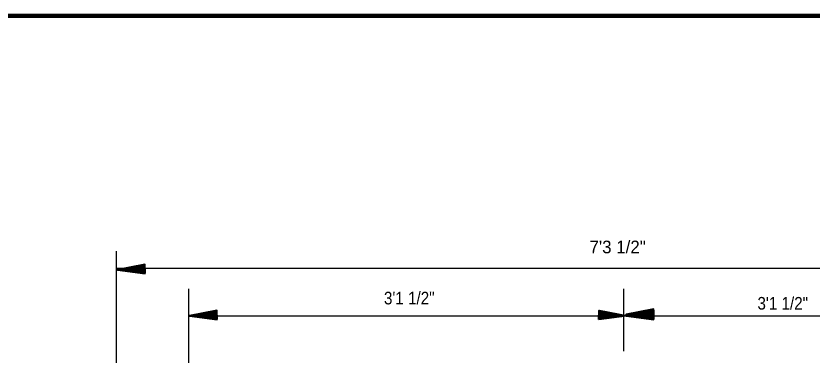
# Model space of a CAD drawing. Extents: x 895.6 to 930.4, y -2278.6 to -2254.7.
# Drawn here: x 911.41 to 919.51, y -2259.61 to -2256.16 of the extents above; entities that cross this region are included whole.
import ezdxf

# ---------------------------------------------------------------- set-up
doc = ezdxf.new("R2010")
doc.units = 0
doc.header["$LTSCALE"] = 0.051
doc.layers.add('1', color=7, linetype='Continuous', lineweight=70)
doc.layers.add('3', color=7, linetype='Continuous', lineweight=40)

msp = doc.modelspace()

# ---------------------------------------------------------------- hatches: boundary and pattern name
at = {"layer": '3'}
for points in [[(912.72933, -2258.78442), (912.72617, -2258.69083), (912.44692, -2258.74717), (912.44692, -2258.74717)], [(912.72783, -2258.77975), (912.72508, -2258.69558), (912.47383, -2258.74617), (912.47383, -2258.74617)], [(912.72667, -2258.77558), (912.72408, -2258.69983), (912.49792, -2258.74542), (912.49792, -2258.74542)], [(912.72542, -2258.77183), (912.72317, -2258.70375), (912.51967, -2258.74475), (912.51967, -2258.74475)], [(912.72458, -2258.76867), (912.72233, -2258.70725), (912.53917, -2258.74417), (912.53917, -2258.74417)], [(912.72333, -2258.76542), (912.72158, -2258.71025), (912.55675, -2258.74358), (912.55675, -2258.74358)], [(912.72267, -2258.76267), (912.72108, -2258.71292), (912.57258, -2258.74292), (912.57258, -2258.74292)], [(912.72175, -2258.76033), (912.72042, -2258.71558), (912.58692, -2258.74258), (912.58692, -2258.74258)], [(912.72133, -2258.75817), (912.71975, -2258.71775), (912.59967, -2258.74192), (912.59967, -2258.74192)], [(912.72058, -2258.75608), (912.71925, -2258.71967), (912.61125, -2258.74167), (912.61125, -2258.74167)], [(912.71992, -2258.75425), (912.71883, -2258.72167), (912.62167, -2258.74125), (912.62167, -2258.74125)], [(912.71958, -2258.75258), (912.71842, -2258.72333), (912.63092, -2258.74083), (912.63092, -2258.74083)], [(912.71892, -2258.75125), (912.71817, -2258.72475), (912.63958, -2258.74067), (912.63958, -2258.74067)], [(912.71842, -2258.74983), (912.71783, -2258.72608), (912.64683, -2258.74042), (912.64683, -2258.74042)], [(912.71817, -2258.74875), (912.71742, -2258.72725), (912.65375, -2258.74025), (912.65375, -2258.74025)], [(912.71783, -2258.74767), (912.71733, -2258.72825), (912.65983, -2258.73983), (912.65983, -2258.73983)], [(912.71758, -2258.74667), (912.71692, -2258.72917), (912.66533, -2258.73967), (912.66533, -2258.73967)], [(912.71733, -2258.74575), (912.71683, -2258.73017), (912.67025, -2258.73958), (912.67025, -2258.73958)], [(912.71692, -2258.74525), (912.71667, -2258.73108), (912.67467, -2258.73958), (912.67467, -2258.73958)], [(912.71675, -2258.74458), (912.71633, -2258.73183), (912.67858, -2258.73942), (912.67858, -2258.73942)], [(912.71642, -2258.74417), (912.71608, -2258.73267), (912.68217, -2258.73967), (912.68217, -2258.73967)], [(912.71642, -2258.74342), (912.71608, -2258.73325), (912.68542, -2258.73942), (912.68542, -2258.73942)], [(912.71625, -2258.74283), (912.71583, -2258.73375), (912.68833, -2258.73917), (912.68833, -2258.73917)], [(912.71608, -2258.74258), (912.71575, -2258.73433), (912.69092, -2258.73925), (912.69092, -2258.73925)], [(913.46083, -2259.25267), (913.45767, -2259.15908), (913.17842, -2259.21533), (913.17842, -2259.21533)], [(913.45933, -2259.24792), (913.45658, -2259.16375), (913.20533, -2259.21433), (913.20533, -2259.21433)], [(913.45817, -2259.24375), (913.45558, -2259.16808), (913.22942, -2259.21367), (913.22942, -2259.21367)], [(913.45692, -2259.24008), (913.45467, -2259.17192), (913.25117, -2259.21292), (913.25117, -2259.21292)], [(913.45608, -2259.23683), (913.45383, -2259.17542), (913.27067, -2259.21233), (913.27067, -2259.21233)], [(917.34267, -2259.25267), (917.34583, -2259.15908), (917.62508, -2259.21533), (917.62508, -2259.21533)], [(917.34417, -2259.24792), (917.34692, -2259.16375), (917.59817, -2259.21433), (917.59817, -2259.21433)], [(917.34533, -2259.24375), (917.34792, -2259.16808), (917.57408, -2259.21367), (917.57408, -2259.21367)], [(917.34658, -2259.24008), (917.34883, -2259.17192), (917.55233, -2259.21292), (917.55233, -2259.21292)], [(917.34742, -2259.23683), (917.34967, -2259.17542), (917.53283, -2259.21233), (917.53283, -2259.21233)], [(917.90175, -2259.23942), (917.89858, -2259.14583), (917.61933, -2259.20217), (917.61933, -2259.20217)], [(917.90183, -2259.25267), (917.89867, -2259.15908), (917.61942, -2259.21533), (917.61942, -2259.21533)], [(917.90025, -2259.23475), (917.89742, -2259.15058), (917.64625, -2259.20117), (917.64625, -2259.20117)], [(917.90033, -2259.24792), (917.89758, -2259.16375), (917.64633, -2259.21433), (917.64633, -2259.21433)], [(917.89908, -2259.23058), (917.89642, -2259.15483), (917.67033, -2259.20042), (917.67033, -2259.20042)], [(917.89917, -2259.24375), (917.89658, -2259.16808), (917.67042, -2259.21367), (917.67042, -2259.21367)], [(917.89783, -2259.22683), (917.89558, -2259.15875), (917.69208, -2259.19975), (917.69208, -2259.19975)], [(917.89792, -2259.24008), (917.89567, -2259.17192), (917.69217, -2259.21292), (917.69217, -2259.21292)], [(917.89692, -2259.22367), (917.89475, -2259.16225), (917.71158, -2259.19917), (917.71158, -2259.19917)], [(917.89708, -2259.23683), (917.89483, -2259.17542), (917.71167, -2259.21233), (917.71167, -2259.21233)], [(917.89575, -2259.22042), (917.89392, -2259.16525), (917.72917, -2259.19858), (917.72917, -2259.19858)], [(917.89508, -2259.21767), (917.89342, -2259.16792), (917.74492, -2259.19792), (917.74492, -2259.19792)], [(917.89417, -2259.21533), (917.89283, -2259.17058), (917.75933, -2259.19758), (917.75933, -2259.19758)], [(917.89375, -2259.21317), (917.89217, -2259.17275), (917.77208, -2259.19692), (917.77208, -2259.19692)], [(917.89292, -2259.21108), (917.89167, -2259.17467), (917.78367, -2259.19667), (917.78367, -2259.19667)], [(917.89233, -2259.20925), (917.89125, -2259.17667), (917.79408, -2259.19625), (917.79408, -2259.19625)], [(913.45483, -2259.23367), (913.45308, -2259.17842), (913.28825, -2259.21175), (913.28825, -2259.21175)], [(913.45417, -2259.23083), (913.45258, -2259.18117), (913.30408, -2259.21117), (913.30408, -2259.21117)], [(913.45325, -2259.22858), (913.45192, -2259.18375), (913.31842, -2259.21075), (913.31842, -2259.21075)], [(913.45283, -2259.22633), (913.45125, -2259.18592), (913.33117, -2259.21017), (913.33117, -2259.21017)], [(913.45208, -2259.22425), (913.45075, -2259.18783), (913.34275, -2259.20983), (913.34275, -2259.20983)], [(913.45142, -2259.22242), (913.45033, -2259.18983), (913.35317, -2259.20942), (913.35317, -2259.20942)], [(913.45108, -2259.22075), (913.44992, -2259.19158), (913.36242, -2259.20908), (913.36242, -2259.20908)], [(913.45042, -2259.21942), (913.44967, -2259.19292), (913.37108, -2259.20883), (913.37108, -2259.20883)], [(913.44992, -2259.21808), (913.44933, -2259.19425), (913.37833, -2259.20867), (913.37833, -2259.20867)], [(913.44967, -2259.21692), (913.44892, -2259.19542), (913.38525, -2259.20842), (913.38525, -2259.20842)], [(913.44933, -2259.21583), (913.44883, -2259.19642), (913.39133, -2259.20808), (913.39133, -2259.20808)], [(913.44908, -2259.21483), (913.44842, -2259.19733), (913.39683, -2259.20783), (913.39683, -2259.20783)], [(913.44883, -2259.21392), (913.44833, -2259.19833), (913.40175, -2259.20775), (913.40175, -2259.20775)], [(913.44842, -2259.21342), (913.44817, -2259.19925), (913.40617, -2259.20775), (913.40617, -2259.20775)], [(913.44825, -2259.21275), (913.44783, -2259.20008), (913.41008, -2259.20767), (913.41008, -2259.20767)], [(913.44792, -2259.21233), (913.44758, -2259.20083), (913.41367, -2259.20783), (913.41367, -2259.20783)], [(913.44792, -2259.21167), (913.44758, -2259.20142), (913.41692, -2259.20767), (913.41692, -2259.20767)], [(913.44775, -2259.21108), (913.44733, -2259.20192), (913.41983, -2259.20733), (913.41983, -2259.20733)], [(913.44758, -2259.21075), (913.44725, -2259.20258), (913.42242, -2259.20742), (913.42242, -2259.20742)], [(917.34867, -2259.23367), (917.35042, -2259.17842), (917.51525, -2259.21175), (917.51525, -2259.21175)], [(917.34933, -2259.23083), (917.35092, -2259.18117), (917.49942, -2259.21117), (917.49942, -2259.21117)], [(917.35025, -2259.22858), (917.35158, -2259.18375), (917.48508, -2259.21075), (917.48508, -2259.21075)], [(917.35067, -2259.22633), (917.35225, -2259.18592), (917.47233, -2259.21017), (917.47233, -2259.21017)], [(917.35142, -2259.22425), (917.35275, -2259.18783), (917.46075, -2259.20983), (917.46075, -2259.20983)], [(917.35208, -2259.22242), (917.35317, -2259.18983), (917.45033, -2259.20942), (917.45033, -2259.20942)], [(917.35242, -2259.22075), (917.35358, -2259.19158), (917.44108, -2259.20908), (917.44108, -2259.20908)], [(917.35308, -2259.21942), (917.35383, -2259.19292), (917.43242, -2259.20883), (917.43242, -2259.20883)], [(917.35358, -2259.21808), (917.35417, -2259.19425), (917.42517, -2259.20867), (917.42517, -2259.20867)], [(917.35383, -2259.21692), (917.35458, -2259.19542), (917.41825, -2259.20842), (917.41825, -2259.20842)], [(917.35417, -2259.21583), (917.35467, -2259.19642), (917.41217, -2259.20808), (917.41217, -2259.20808)], [(917.35442, -2259.21483), (917.35508, -2259.19733), (917.40667, -2259.20783), (917.40667, -2259.20783)], [(917.35467, -2259.21392), (917.35517, -2259.19833), (917.40175, -2259.20775), (917.40175, -2259.20775)], [(917.35508, -2259.21342), (917.35533, -2259.19925), (917.39733, -2259.20775), (917.39733, -2259.20775)], [(917.35525, -2259.21275), (917.35567, -2259.20008), (917.39342, -2259.20767), (917.39342, -2259.20767)], [(917.35558, -2259.21233), (917.35592, -2259.20083), (917.38983, -2259.20783), (917.38983, -2259.20783)], [(917.35558, -2259.21167), (917.35592, -2259.20142), (917.38658, -2259.20767), (917.38658, -2259.20767)], [(917.35575, -2259.21108), (917.35617, -2259.20192), (917.38367, -2259.20733), (917.38367, -2259.20733)], [(917.35592, -2259.21075), (917.35625, -2259.20258), (917.38108, -2259.20742), (917.38108, -2259.20742)], [(917.89583, -2259.23367), (917.89408, -2259.17842), (917.72925, -2259.21175), (917.72925, -2259.21175)], [(917.89517, -2259.23083), (917.89358, -2259.18117), (917.74508, -2259.21117), (917.74508, -2259.21117)], [(917.89425, -2259.22858), (917.89292, -2259.18375), (917.75942, -2259.21075), (917.75942, -2259.21075)], [(917.89383, -2259.22633), (917.89225, -2259.18592), (917.77217, -2259.21017), (917.77217, -2259.21017)], [(917.89308, -2259.22425), (917.89175, -2259.18783), (917.78375, -2259.20983), (917.78375, -2259.20983)], [(917.89242, -2259.22242), (917.89133, -2259.18983), (917.79417, -2259.20942), (917.79417, -2259.20942)], [(917.89192, -2259.20758), (917.89083, -2259.17833), (917.80333, -2259.19583), (917.80333, -2259.19583)], [(917.89208, -2259.22075), (917.89092, -2259.19158), (917.80342, -2259.20908), (917.80342, -2259.20908)], [(917.89133, -2259.20625), (917.89058, -2259.17975), (917.81192, -2259.19567), (917.81192, -2259.19567)], [(917.89142, -2259.21942), (917.89067, -2259.19292), (917.81208, -2259.20883), (917.81208, -2259.20883)], [(917.89083, -2259.20483), (917.89025, -2259.18108), (917.81925, -2259.19542), (917.81925, -2259.19542)], [(917.89092, -2259.21808), (917.89033, -2259.19425), (917.81933, -2259.20867), (917.81933, -2259.20867)], [(917.89058, -2259.20375), (917.88983, -2259.18225), (917.82617, -2259.19525), (917.82617, -2259.19525)], [(917.89067, -2259.21692), (917.88992, -2259.19542), (917.82625, -2259.20842), (917.82625, -2259.20842)], [(917.89025, -2259.20267), (917.88975, -2259.18325), (917.83225, -2259.19483), (917.83225, -2259.19483)], [(917.89033, -2259.21583), (917.88983, -2259.19642), (917.83233, -2259.20808), (917.83233, -2259.20808)], [(917.88992, -2259.20167), (917.88933, -2259.18417), (917.83775, -2259.19467), (917.83775, -2259.19467)], [(917.89008, -2259.21483), (917.88942, -2259.19733), (917.83783, -2259.20783), (917.83783, -2259.20783)], [(917.88975, -2259.20075), (917.88925, -2259.18517), (917.84267, -2259.19458), (917.84267, -2259.19458)], [(917.88983, -2259.21392), (917.88933, -2259.19833), (917.84275, -2259.20775), (917.84275, -2259.20775)], [(917.88933, -2259.20025), (917.88908, -2259.18608), (917.84708, -2259.19458), (917.84708, -2259.19458)], [(917.88942, -2259.21342), (917.88917, -2259.19925), (917.84717, -2259.20775), (917.84717, -2259.20775)], [(917.88917, -2259.19958), (917.88875, -2259.18683), (917.85092, -2259.19442), (917.85092, -2259.19442)], [(917.88925, -2259.21275), (917.88883, -2259.20008), (917.85108, -2259.20767), (917.85108, -2259.20767)], [(917.88883, -2259.19917), (917.88842, -2259.18767), (917.85458, -2259.19467), (917.85458, -2259.19467)], [(917.88892, -2259.21233), (917.88858, -2259.20083), (917.85467, -2259.20783), (917.85467, -2259.20783)], [(917.88883, -2259.19842), (917.88842, -2259.18825), (917.85783, -2259.19442), (917.85783, -2259.19442)], [(917.88892, -2259.21167), (917.88858, -2259.20142), (917.85792, -2259.20767), (917.85792, -2259.20767)], [(917.88867, -2259.19783), (917.88825, -2259.18875), (917.86075, -2259.19417), (917.86075, -2259.19417)], [(917.88875, -2259.21108), (917.88833, -2259.20192), (917.86083, -2259.20733), (917.86083, -2259.20733)], [(917.88842, -2259.19758), (917.88817, -2259.18933), (917.86333, -2259.19425), (917.86333, -2259.19425)], [(917.88858, -2259.21075), (917.88825, -2259.20258), (917.86342, -2259.20742), (917.86342, -2259.20742)]]:
    msp.add_hatch(color=256, dxfattribs=at).paths.add_polyline_path(points)

# ---------------------------------------------------------------- linework, layer by layer
at = {"layer": '1', "lineweight": 25}
for p, q in [((912.43625, -2260.80017), (912.43625, -2258.55592)), ((912.43625, -2258.73083), (922.81042, -2258.73083)), ((913.17308, -2260.87842), (913.17308, -2258.93908)), ((917.59408, -2259.57383), (917.59408, -2258.93908)), ((913.17308, -2259.21358), (922.07417, -2259.21358))]:
    msp.add_line(p, q, dxfattribs=at)
at = {"layer": '3', "lineweight": 158}
msp.add_line((929.94183, -2256.16333), (897.44183, -2256.16333), dxfattribs=at)
at = {"layer": '3'}
for points in [[(912.72933, -2258.78442), (912.72617, -2258.69083), (912.44692, -2258.74717), (912.44692, -2258.74717)], [(912.72783, -2258.77975), (912.72508, -2258.69558), (912.47383, -2258.74617), (912.47383, -2258.74617)], [(912.72667, -2258.77558), (912.72408, -2258.69983), (912.49792, -2258.74542), (912.49792, -2258.74542)], [(912.72542, -2258.77183), (912.72317, -2258.70375), (912.51967, -2258.74475), (912.51967, -2258.74475)], [(912.72458, -2258.76867), (912.72233, -2258.70725), (912.53917, -2258.74417), (912.53917, -2258.74417)], [(912.72333, -2258.76542), (912.72158, -2258.71025), (912.55675, -2258.74358), (912.55675, -2258.74358)], [(912.72267, -2258.76267), (912.72108, -2258.71292), (912.57258, -2258.74292), (912.57258, -2258.74292)], [(912.72175, -2258.76033), (912.72042, -2258.71558), (912.58692, -2258.74258), (912.58692, -2258.74258)], [(912.72133, -2258.75817), (912.71975, -2258.71775), (912.59967, -2258.74192), (912.59967, -2258.74192)], [(912.72058, -2258.75608), (912.71925, -2258.71967), (912.61125, -2258.74167), (912.61125, -2258.74167)], [(912.71992, -2258.75425), (912.71883, -2258.72167), (912.62167, -2258.74125), (912.62167, -2258.74125)], [(912.71958, -2258.75258), (912.71842, -2258.72333), (912.63092, -2258.74083), (912.63092, -2258.74083)], [(912.71892, -2258.75125), (912.71817, -2258.72475), (912.63958, -2258.74067), (912.63958, -2258.74067)], [(912.71842, -2258.74983), (912.71783, -2258.72608), (912.64683, -2258.74042), (912.64683, -2258.74042)], [(912.71817, -2258.74875), (912.71742, -2258.72725), (912.65375, -2258.74025), (912.65375, -2258.74025)], [(912.71783, -2258.74767), (912.71733, -2258.72825), (912.65983, -2258.73983), (912.65983, -2258.73983)], [(912.71758, -2258.74667), (912.71692, -2258.72917), (912.66533, -2258.73967), (912.66533, -2258.73967)], [(912.71733, -2258.74575), (912.71683, -2258.73017), (912.67025, -2258.73958), (912.67025, -2258.73958)], [(912.71692, -2258.74525), (912.71667, -2258.73108), (912.67467, -2258.73958), (912.67467, -2258.73958)], [(912.71675, -2258.74458), (912.71633, -2258.73183), (912.67858, -2258.73942), (912.67858, -2258.73942)], [(912.71642, -2258.74417), (912.71608, -2258.73267), (912.68217, -2258.73967), (912.68217, -2258.73967)], [(912.71642, -2258.74342), (912.71608, -2258.73325), (912.68542, -2258.73942), (912.68542, -2258.73942)], [(912.71625, -2258.74283), (912.71583, -2258.73375), (912.68833, -2258.73917), (912.68833, -2258.73917)], [(912.71608, -2258.74258), (912.71575, -2258.73433), (912.69092, -2258.73925), (912.69092, -2258.73925)], [(913.46083, -2259.25267), (913.45767, -2259.15908), (913.17842, -2259.21533), (913.17842, -2259.21533)], [(913.45933, -2259.24792), (913.45658, -2259.16375), (913.20533, -2259.21433), (913.20533, -2259.21433)], [(913.45817, -2259.24375), (913.45558, -2259.16808), (913.22942, -2259.21367), (913.22942, -2259.21367)], [(913.45692, -2259.24008), (913.45467, -2259.17192), (913.25117, -2259.21292), (913.25117, -2259.21292)], [(913.45608, -2259.23683), (913.45383, -2259.17542), (913.27067, -2259.21233), (913.27067, -2259.21233)], [(917.34267, -2259.25267), (917.34583, -2259.15908), (917.62508, -2259.21533), (917.62508, -2259.21533)], [(917.34417, -2259.24792), (917.34692, -2259.16375), (917.59817, -2259.21433), (917.59817, -2259.21433)], [(917.34533, -2259.24375), (917.34792, -2259.16808), (917.57408, -2259.21367), (917.57408, -2259.21367)], [(917.34658, -2259.24008), (917.34883, -2259.17192), (917.55233, -2259.21292), (917.55233, -2259.21292)], [(917.34742, -2259.23683), (917.34967, -2259.17542), (917.53283, -2259.21233), (917.53283, -2259.21233)], [(917.90175, -2259.23942), (917.89858, -2259.14583), (917.61933, -2259.20217), (917.61933, -2259.20217)], [(917.90183, -2259.25267), (917.89867, -2259.15908), (917.61942, -2259.21533), (917.61942, -2259.21533)], [(917.90025, -2259.23475), (917.89742, -2259.15058), (917.64625, -2259.20117), (917.64625, -2259.20117)], [(917.90033, -2259.24792), (917.89758, -2259.16375), (917.64633, -2259.21433), (917.64633, -2259.21433)], [(917.89908, -2259.23058), (917.89642, -2259.15483), (917.67033, -2259.20042), (917.67033, -2259.20042)], [(917.89917, -2259.24375), (917.89658, -2259.16808), (917.67042, -2259.21367), (917.67042, -2259.21367)], [(917.89783, -2259.22683), (917.89558, -2259.15875), (917.69208, -2259.19975), (917.69208, -2259.19975)], [(917.89792, -2259.24008), (917.89567, -2259.17192), (917.69217, -2259.21292), (917.69217, -2259.21292)], [(917.89692, -2259.22367), (917.89475, -2259.16225), (917.71158, -2259.19917), (917.71158, -2259.19917)], [(917.89708, -2259.23683), (917.89483, -2259.17542), (917.71167, -2259.21233), (917.71167, -2259.21233)], [(917.89575, -2259.22042), (917.89392, -2259.16525), (917.72917, -2259.19858), (917.72917, -2259.19858)], [(917.89508, -2259.21767), (917.89342, -2259.16792), (917.74492, -2259.19792), (917.74492, -2259.19792)], [(917.89417, -2259.21533), (917.89283, -2259.17058), (917.75933, -2259.19758), (917.75933, -2259.19758)], [(917.89375, -2259.21317), (917.89217, -2259.17275), (917.77208, -2259.19692), (917.77208, -2259.19692)], [(917.89292, -2259.21108), (917.89167, -2259.17467), (917.78367, -2259.19667), (917.78367, -2259.19667)], [(917.89233, -2259.20925), (917.89125, -2259.17667), (917.79408, -2259.19625), (917.79408, -2259.19625)], [(913.45483, -2259.23367), (913.45308, -2259.17842), (913.28825, -2259.21175), (913.28825, -2259.21175)], [(913.45417, -2259.23083), (913.45258, -2259.18117), (913.30408, -2259.21117), (913.30408, -2259.21117)], [(913.45325, -2259.22858), (913.45192, -2259.18375), (913.31842, -2259.21075), (913.31842, -2259.21075)], [(913.45283, -2259.22633), (913.45125, -2259.18592), (913.33117, -2259.21017), (913.33117, -2259.21017)], [(913.45208, -2259.22425), (913.45075, -2259.18783), (913.34275, -2259.20983), (913.34275, -2259.20983)], [(913.45142, -2259.22242), (913.45033, -2259.18983), (913.35317, -2259.20942), (913.35317, -2259.20942)], [(913.45108, -2259.22075), (913.44992, -2259.19158), (913.36242, -2259.20908), (913.36242, -2259.20908)], [(913.45042, -2259.21942), (913.44967, -2259.19292), (913.37108, -2259.20883), (913.37108, -2259.20883)], [(913.44992, -2259.21808), (913.44933, -2259.19425), (913.37833, -2259.20867), (913.37833, -2259.20867)], [(913.44967, -2259.21692), (913.44892, -2259.19542), (913.38525, -2259.20842), (913.38525, -2259.20842)], [(913.44933, -2259.21583), (913.44883, -2259.19642), (913.39133, -2259.20808), (913.39133, -2259.20808)], [(913.44908, -2259.21483), (913.44842, -2259.19733), (913.39683, -2259.20783), (913.39683, -2259.20783)], [(913.44883, -2259.21392), (913.44833, -2259.19833), (913.40175, -2259.20775), (913.40175, -2259.20775)], [(913.44842, -2259.21342), (913.44817, -2259.19925), (913.40617, -2259.20775), (913.40617, -2259.20775)], [(913.44825, -2259.21275), (913.44783, -2259.20008), (913.41008, -2259.20767), (913.41008, -2259.20767)], [(913.44792, -2259.21233), (913.44758, -2259.20083), (913.41367, -2259.20783), (913.41367, -2259.20783)], [(913.44792, -2259.21167), (913.44758, -2259.20142), (913.41692, -2259.20767), (913.41692, -2259.20767)], [(913.44775, -2259.21108), (913.44733, -2259.20192), (913.41983, -2259.20733), (913.41983, -2259.20733)], [(913.44758, -2259.21075), (913.44725, -2259.20258), (913.42242, -2259.20742), (913.42242, -2259.20742)], [(917.34867, -2259.23367), (917.35042, -2259.17842), (917.51525, -2259.21175), (917.51525, -2259.21175)], [(917.34933, -2259.23083), (917.35092, -2259.18117), (917.49942, -2259.21117), (917.49942, -2259.21117)], [(917.35025, -2259.22858), (917.35158, -2259.18375), (917.48508, -2259.21075), (917.48508, -2259.21075)], [(917.35067, -2259.22633), (917.35225, -2259.18592), (917.47233, -2259.21017), (917.47233, -2259.21017)], [(917.35142, -2259.22425), (917.35275, -2259.18783), (917.46075, -2259.20983), (917.46075, -2259.20983)], [(917.35208, -2259.22242), (917.35317, -2259.18983), (917.45033, -2259.20942), (917.45033, -2259.20942)], [(917.35242, -2259.22075), (917.35358, -2259.19158), (917.44108, -2259.20908), (917.44108, -2259.20908)], [(917.35308, -2259.21942), (917.35383, -2259.19292), (917.43242, -2259.20883), (917.43242, -2259.20883)], [(917.35358, -2259.21808), (917.35417, -2259.19425), (917.42517, -2259.20867), (917.42517, -2259.20867)], [(917.35383, -2259.21692), (917.35458, -2259.19542), (917.41825, -2259.20842), (917.41825, -2259.20842)], [(917.35417, -2259.21583), (917.35467, -2259.19642), (917.41217, -2259.20808), (917.41217, -2259.20808)], [(917.35442, -2259.21483), (917.35508, -2259.19733), (917.40667, -2259.20783), (917.40667, -2259.20783)], [(917.35467, -2259.21392), (917.35517, -2259.19833), (917.40175, -2259.20775), (917.40175, -2259.20775)], [(917.35508, -2259.21342), (917.35533, -2259.19925), (917.39733, -2259.20775), (917.39733, -2259.20775)], [(917.35525, -2259.21275), (917.35567, -2259.20008), (917.39342, -2259.20767), (917.39342, -2259.20767)], [(917.35558, -2259.21233), (917.35592, -2259.20083), (917.38983, -2259.20783), (917.38983, -2259.20783)], [(917.35558, -2259.21167), (917.35592, -2259.20142), (917.38658, -2259.20767), (917.38658, -2259.20767)], [(917.35575, -2259.21108), (917.35617, -2259.20192), (917.38367, -2259.20733), (917.38367, -2259.20733)], [(917.35592, -2259.21075), (917.35625, -2259.20258), (917.38108, -2259.20742), (917.38108, -2259.20742)], [(917.89583, -2259.23367), (917.89408, -2259.17842), (917.72925, -2259.21175), (917.72925, -2259.21175)], [(917.89517, -2259.23083), (917.89358, -2259.18117), (917.74508, -2259.21117), (917.74508, -2259.21117)], [(917.89425, -2259.22858), (917.89292, -2259.18375), (917.75942, -2259.21075), (917.75942, -2259.21075)], [(917.89383, -2259.22633), (917.89225, -2259.18592), (917.77217, -2259.21017), (917.77217, -2259.21017)], [(917.89308, -2259.22425), (917.89175, -2259.18783), (917.78375, -2259.20983), (917.78375, -2259.20983)], [(917.89242, -2259.22242), (917.89133, -2259.18983), (917.79417, -2259.20942), (917.79417, -2259.20942)], [(917.89192, -2259.20758), (917.89083, -2259.17833), (917.80333, -2259.19583), (917.80333, -2259.19583)], [(917.89208, -2259.22075), (917.89092, -2259.19158), (917.80342, -2259.20908), (917.80342, -2259.20908)], [(917.89133, -2259.20625), (917.89058, -2259.17975), (917.81192, -2259.19567), (917.81192, -2259.19567)], [(917.89142, -2259.21942), (917.89067, -2259.19292), (917.81208, -2259.20883), (917.81208, -2259.20883)], [(917.89083, -2259.20483), (917.89025, -2259.18108), (917.81925, -2259.19542), (917.81925, -2259.19542)], [(917.89092, -2259.21808), (917.89033, -2259.19425), (917.81933, -2259.20867), (917.81933, -2259.20867)], [(917.89058, -2259.20375), (917.88983, -2259.18225), (917.82617, -2259.19525), (917.82617, -2259.19525)], [(917.89067, -2259.21692), (917.88992, -2259.19542), (917.82625, -2259.20842), (917.82625, -2259.20842)], [(917.89025, -2259.20267), (917.88975, -2259.18325), (917.83225, -2259.19483), (917.83225, -2259.19483)], [(917.89033, -2259.21583), (917.88983, -2259.19642), (917.83233, -2259.20808), (917.83233, -2259.20808)], [(917.88992, -2259.20167), (917.88933, -2259.18417), (917.83775, -2259.19467), (917.83775, -2259.19467)], [(917.89008, -2259.21483), (917.88942, -2259.19733), (917.83783, -2259.20783), (917.83783, -2259.20783)], [(917.88975, -2259.20075), (917.88925, -2259.18517), (917.84267, -2259.19458), (917.84267, -2259.19458)], [(917.88983, -2259.21392), (917.88933, -2259.19833), (917.84275, -2259.20775), (917.84275, -2259.20775)], [(917.88933, -2259.20025), (917.88908, -2259.18608), (917.84708, -2259.19458), (917.84708, -2259.19458)], [(917.88942, -2259.21342), (917.88917, -2259.19925), (917.84717, -2259.20775), (917.84717, -2259.20775)], [(917.88917, -2259.19958), (917.88875, -2259.18683), (917.85092, -2259.19442), (917.85092, -2259.19442)], [(917.88925, -2259.21275), (917.88883, -2259.20008), (917.85108, -2259.20767), (917.85108, -2259.20767)], [(917.88883, -2259.19917), (917.88842, -2259.18767), (917.85458, -2259.19467), (917.85458, -2259.19467)], [(917.88892, -2259.21233), (917.88858, -2259.20083), (917.85467, -2259.20783), (917.85467, -2259.20783)], [(917.88883, -2259.19842), (917.88842, -2259.18825), (917.85783, -2259.19442), (917.85783, -2259.19442)], [(917.88892, -2259.21167), (917.88858, -2259.20142), (917.85792, -2259.20767), (917.85792, -2259.20767)], [(917.88867, -2259.19783), (917.88825, -2259.18875), (917.86075, -2259.19417), (917.86075, -2259.19417)], [(917.88875, -2259.21108), (917.88833, -2259.20192), (917.86083, -2259.20733), (917.86083, -2259.20733)], [(917.88842, -2259.19758), (917.88817, -2259.18933), (917.86333, -2259.19425), (917.86333, -2259.19425)], [(917.88858, -2259.21075), (917.88825, -2259.20258), (917.86342, -2259.20742), (917.86342, -2259.20742)]]:
    msp.add_lwpolyline(points, close=True, dxfattribs=at)

# ---------------------------------------------------------------- texts
at = {"layer": '1'}
msp.add_text('7\'3 1/2"', height=0.1286, dxfattribs=at).set_placement((917.24625, -2258.57808))
at = {"layer": '1', "width": 0.9}
for p in [(915.15642, -2259.09808), (918.95367, -2259.15108)]:
    msp.add_text('3\'1 1/2"', height=0.1286, dxfattribs=at).set_placement(p)

doc.saveas('drawing.dxf')
